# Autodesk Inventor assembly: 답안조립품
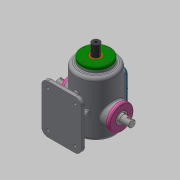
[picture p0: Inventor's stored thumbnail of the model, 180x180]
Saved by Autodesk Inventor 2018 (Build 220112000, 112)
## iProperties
Created: 2021-11
Part Number: 답안조립품
Material: 일반
Document SubType Name: Assembly
Designer: home
Author: home
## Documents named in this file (14)
- C:\Users\home\Desktop\711106V1033\답안조립품.iam
- C:\Users\home\Desktop\711106V1033\본체.ipt
- C:\Users\home\Desktop\711106V1033\축 커버.ipt
- C:\Users\home\Desktop\711106V1033\베어링 6205.ipt
- 베어링 6205.ipt
- C:\Users\home\Desktop\711106V1033\편심축.ipt
- C:\Users\home\Desktop\711106V1033\오일실.ipt
- 오일실.ipt
- C:\Users\home\Desktop\711106V1033\부시.ipt
- C:\Users\home\Desktop\711106V1033\슬라이드 커버.ipt
- C:\Users\home\Desktop\711106V1033\슬라이드.ipt
- C:\Users\home\Desktop\711106V1033\상부커버.ipt
- C:\Users\home\Desktop\711106V1033\육각머리볼트 M4.ipt
- C:\Users\home\Desktop\711106V1033\볼트 M4x0.7.ipt
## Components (12 placed, 1 different names)
1. M4x0.7:1
2. M4x0.7:4
3. M4x0.7:5
4. M4x0.7:6
5. M4x0.7:2
6. M4x0.7:7
7. M4x0.7:8
8. M4x0.7:9
9. M4x0.7:3
10. M4x0.7:10
11. M4x0.7:11
12. M4x0.7:12
